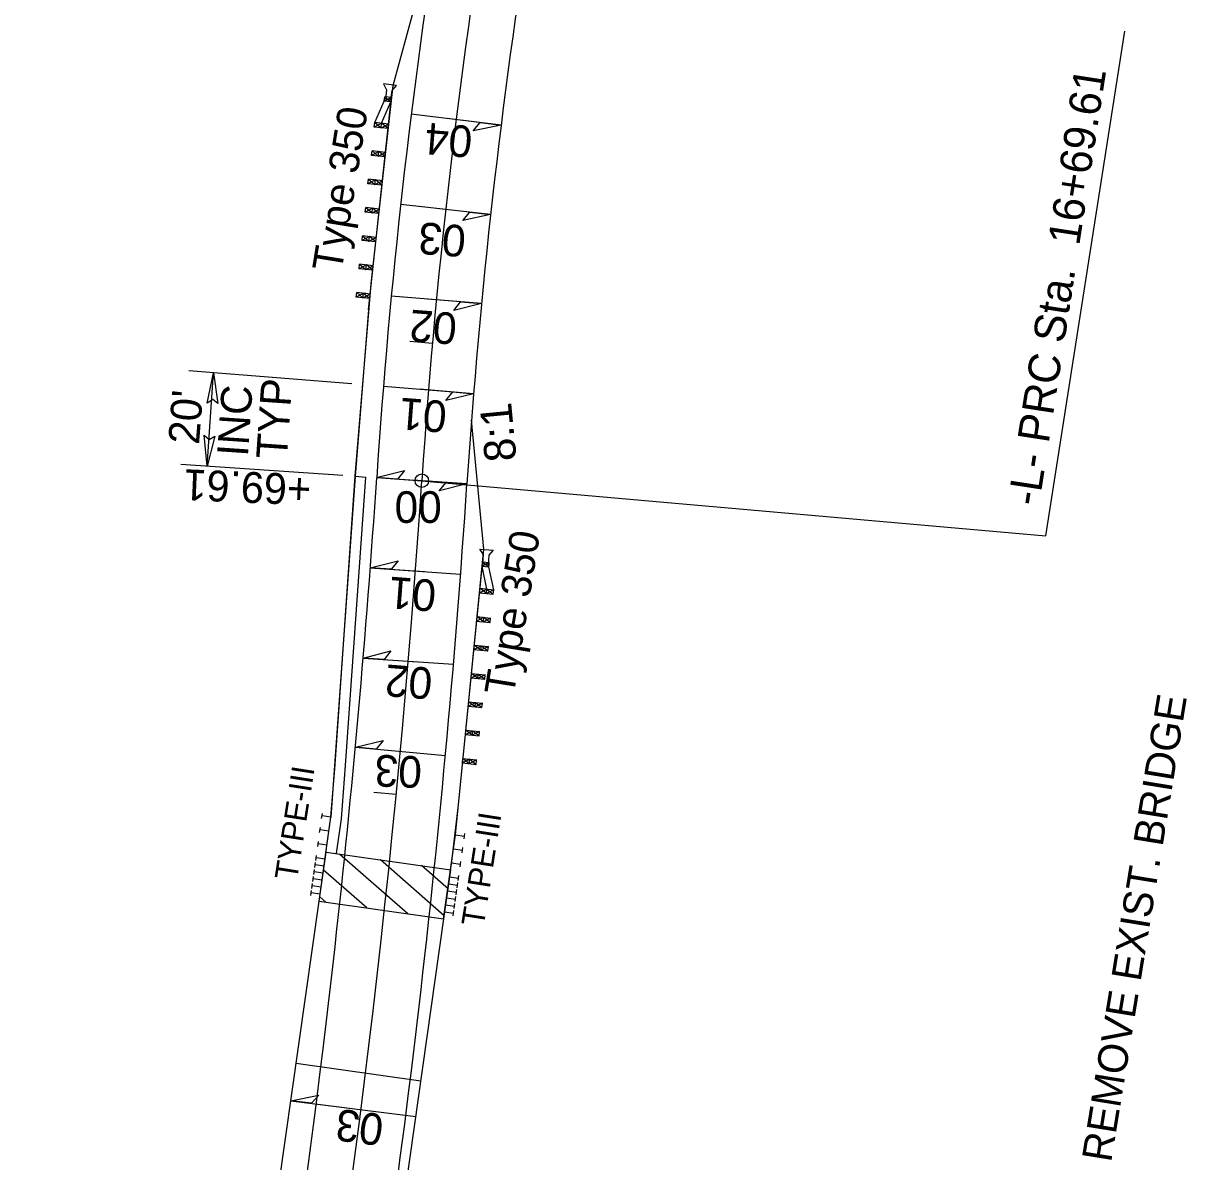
# Model space of a CAD drawing. Extents: x 1698814 to 1699654, y 708133 to 709468.
# Drawn here: x 1699331.8 to 1699588.9, y 708760.1 to 709011.7 of the extents above; entities that cross this region are included whole.
import ezdxf

# ---------------------------------------------------------------- set-up
doc = ezdxf.new("R2010")
doc.units = 0
for name, color, linetype in [('Prop Approach Slab', 7, 'Continuous'), ('Prop Approach Slab Hatching', 7, 'Continuous'), ('Prop Conc Shoulder Berm Gutter', 7, 'Continuous'), ('Prop Dimension', 7, 'Continuous'), ('Prop EOT', 7, 'Continuous'), ('Prop Guardrail', 7, 'Continuous'), ('Prop Guardrail Anchor Unit CELL', 7, 'Continuous'), ('Prop Horizontal Alignment', 7, 'Continuous'), ('Prop Horizontal Alignment Station Label', 7, 'Continuous'), ('Prop Horizontal Alignment Tick Small', 7, 'Continuous'), ('Prop Paved Shoulder', 7, 'Continuous'), ('Prop Roadway Bridge', 7, 'Continuous'), ('Prop Structure Anchor Unit CELL', 7, 'Continuous'), ('Prop Superelevation  Arrow CELL', 7, 'Continuous'), ('Prop Superelevation Label', 7, 'Continuous'), ('Prop Terminator CELL', 7, 'Continuous')]:
    doc.layers.add(name, color=color, linetype=linetype)

msp = doc.modelspace()

# ---------------------------------------------------------------- linework, layer by layer
at = {"layer": 'Prop Approach Slab'}
for p, q in [((1699397.2, 708817.65), (1699398.74, 708828.5)), ((1699398.74, 708828.5), (1699426.29, 708824.6)), ((1699424.76, 708813.74), (1699426.3, 708824.6))]:
    msp.add_line(p, q, dxfattribs=at)
at = {"layer": 'Prop Approach Slab Hatching'}
for p, q in [((1699416.8, 708814.87), (1699401.72, 708828.08)), ((1699407.74, 708816.15), (1699398.18, 708824.54)), ((1699424.86, 708814.45), (1699410.77, 708826.8)), ((1699425.79, 708820.29), (1699419.82, 708825.51)), ((1699398.69, 708817.44), (1699397.36, 708818.6))]:
    msp.add_line(p, q, dxfattribs=at)
at = {"layer": 'Prop Conc Shoulder Berm Gutter'}
for p, q in [((1699400.72, 708847.85), (1699405.21, 708911.57)), ((1699399.83, 708836.21), (1699400.72, 708847.85)), ((1699398.71, 708828.32), (1699399.83, 708836.21)), ((1699426.27, 708824.41), (1699426.55, 708826.39))]:
    msp.add_line(p, q, dxfattribs=at)
at = {"layer": 'Prop Dimension'}
for p, q in [((1699404.43, 708932.01), (1699368.45, 708934.91)), ((1699372.47, 708913.83), (1699373.88, 708934.48)), ((1699366.65, 708914.22), (1699402.43, 708911.79))]:
    msp.add_line(p, q, dxfattribs=at)
at = {"layer": 'Prop EOT'}
msp.add_line((1699411.63, 708815.6), (1699411.63, 708815.6), dxfattribs=at)
for centre, radius, start, end in [((1700816.84, 708818.02), 1410, 165.74431, 176.20849), ((1700816.84, 708818.02), 1390, 165.7259, 176.20849), ((1697132.82, 709061.2), 2282.04, 353.61848, 356.23256), ((1697124.94, 709062.69), 2310, 350.26654, 356.20849), ((1697132.82, 709061.2), 2282.04, 344.49766, 353.61848)]:
    msp.add_arc(centre, radius, start, end, dxfattribs=at)
at = {"layer": 'Prop Guardrail'}
for p, q in [((1699408.12, 708948.34), (1699405.21, 708911.57)), ((1699405.21, 708911.57), (1699399.83, 708836.21)), ((1699427.33, 708832.32), (1699428.65, 708845.67))]:
    msp.add_line(p, q, dxfattribs=at)
at = {"layer": 'Prop Guardrail Anchor Unit CELL'}
for p, q in [((1699414.32, 708997.95), (1699411.4, 708998.32)), ((1699411.4, 708998.32), (1699412.11, 708997.04)), ((1699412.11, 708997.04), (1699411.85, 708995.01)), ((1699413.06, 708994.86), (1699413.32, 708996.89)), ((1699413.32, 708996.89), (1699414.32, 708997.95)), ((1699408.12, 708948.34), (1699413.14, 708994.82)), ((1699409.51, 708989.78), (1699411.59, 708994.48)), ((1699411.03, 708989.61), (1699413.08, 708994.32)), ((1699411.59, 708994.48), (1699411.7, 708995.48)), ((1699413.19, 708995.32), (1699411.59, 708994.48)), ((1699411.59, 708994.48), (1699411.64, 708994.98)), ((1699413.08, 708994.32), (1699411.59, 708994.48)), ((1699413.19, 708995.32), (1699411.7, 708995.48)), ((1699411.7, 708995.48), (1699413.08, 708994.32)), ((1699411.85, 708995.01), (1699412.46, 708994.93)), ((1699412.46, 708994.93), (1699413.06, 708994.86)), ((1699409.4, 708988.78), (1699409.51, 708989.78)), ((1699411.03, 708989.61), (1699409.4, 708988.78)), ((1699412.56, 708989.45), (1699409.51, 708989.78)), ((1699409.51, 708989.78), (1699410.93, 708988.62)), ((1699410.93, 708988.62), (1699411.03, 708989.61)), ((1699410.93, 708988.62), (1699412.56, 708989.45)), ((1699412.45, 708988.45), (1699411.03, 708989.61)), ((1699412.45, 708988.45), (1699409.4, 708988.78)), ((1699408.79, 708982.51), (1699408.9, 708983.51)), ((1699410.39, 708983.34), (1699408.79, 708982.51)), ((1699411.77, 708982.19), (1699408.79, 708982.51)), ((1699411.88, 708983.18), (1699408.9, 708983.51)), ((1699408.9, 708983.51), (1699410.28, 708982.35)), ((1699410.28, 708982.35), (1699410.39, 708983.34)), ((1699410.28, 708982.35), (1699411.88, 708983.18)), ((1699411.77, 708982.19), (1699410.39, 708983.34)), ((1699407.98, 708976.26), (1699408.09, 708977.25)), ((1699409.65, 708977.09), (1699407.98, 708976.26)), ((1699411.1, 708975.92), (1699407.98, 708976.26)), ((1699411.21, 708976.92), (1699408.09, 708977.25)), ((1699408.09, 708977.25), (1699409.54, 708976.09)), ((1699409.54, 708976.09), (1699409.65, 708977.09)), ((1699409.54, 708976.09), (1699411.21, 708976.92)), ((1699411.1, 708975.92), (1699409.65, 708977.09)), ((1699407.4, 708969.98), (1699407.51, 708970.98)), ((1699410.53, 708970.65), (1699407.51, 708970.98)), ((1699407.51, 708970.98), (1699408.91, 708969.82)), ((1699409.02, 708970.82), (1699407.4, 708969.98)), ((1699410.42, 708969.66), (1699407.4, 708969.98)), ((1699408.91, 708969.82), (1699409.02, 708970.82)), ((1699408.91, 708969.82), (1699410.53, 708970.65)), ((1699410.42, 708969.66), (1699409.02, 708970.82)), ((1699410.42, 708969.66), (1699410.53, 708970.65)), ((1699406.72, 708963.72), (1699406.82, 708964.72)), ((1699408.34, 708964.55), (1699406.72, 708963.72)), ((1699409.75, 708963.39), (1699406.72, 708963.72)), ((1699409.85, 708964.39), (1699406.82, 708964.72)), ((1699406.82, 708964.72), (1699408.23, 708963.56)), ((1699408.23, 708963.56), (1699408.34, 708964.55)), ((1699408.23, 708963.56), (1699409.85, 708964.39)), ((1699409.75, 708963.39), (1699408.34, 708964.55)), ((1699406.04, 708957.46), (1699406.14, 708958.45)), ((1699407.66, 708958.29), (1699406.04, 708957.46)), ((1699409.18, 708958.12), (1699406.14, 708958.45)), ((1699406.14, 708958.45), (1699407.55, 708957.29)), ((1699407.55, 708957.29), (1699407.66, 708958.29)), ((1699407.55, 708957.29), (1699409.18, 708958.12)), ((1699409.07, 708957.13), (1699407.66, 708958.29)), ((1699409.07, 708957.13), (1699406.04, 708957.46)), ((1699405.41, 708951.19), (1699405.52, 708952.18)), ((1699407.01, 708952.02), (1699405.41, 708951.19)), ((1699408.4, 708950.86), (1699405.41, 708951.19)), ((1699408.5, 708951.86), (1699405.52, 708952.18)), ((1699405.52, 708952.18), (1699406.9, 708951.03)), ((1699406.9, 708951.03), (1699407.01, 708952.02)), ((1699406.9, 708951.03), (1699408.5, 708951.86)), ((1699408.5, 708951.86), (1699407.01, 708952.02)), ((1699407.01, 708952.02), (1699408.4, 708950.86)), ((1699408.4, 708950.86), (1699408.5, 708951.86)), ((1699433.53, 708894.26), (1699432.76, 708895.5)), ((1699432.76, 708895.5), (1699435.69, 708895.26)), ((1699433.36, 708892.21), (1699433.53, 708894.26)), ((1699434.74, 708894.15), (1699434.58, 708892.11)), ((1699435.69, 708895.26), (1699434.74, 708894.15)), ((1699428.65, 708845.67), (1699433.28, 708892.19)), ((1699434.82, 708892.54), (1699433.23, 708891.69)), ((1699433.23, 708891.69), (1699434.73, 708891.54)), ((1699434.27, 708886.66), (1699433.23, 708891.69)), ((1699433.33, 708892.69), (1699434.82, 708892.54)), ((1699433.33, 708892.69), (1699434.73, 708891.54)), ((1699433.97, 708892.16), (1699433.36, 708892.21)), ((1699434.58, 708892.11), (1699433.97, 708892.16)), ((1699434.73, 708891.54), (1699434.82, 708892.54)), ((1699434.73, 708891.54), (1699434.77, 708892.04)), ((1699435.8, 708886.51), (1699434.73, 708891.54)), ((1699432.65, 708885.82), (1699434.27, 708886.66)), ((1699432.75, 708886.82), (1699435.8, 708886.51)), ((1699434.17, 708885.67), (1699432.75, 708886.82)), ((1699434.17, 708885.67), (1699434.27, 708886.66)), ((1699435.8, 708886.51), (1699434.17, 708885.67)), ((1699434.27, 708886.66), (1699435.7, 708885.52)), ((1699435.7, 708885.52), (1699435.8, 708886.51)), ((1699432.65, 708885.82), (1699435.7, 708885.52)), ((1699432.02, 708879.55), (1699433.62, 708880.4)), ((1699432.02, 708879.55), (1699435.01, 708879.25)), ((1699432.12, 708880.55), (1699435.11, 708880.25)), ((1699433.52, 708879.4), (1699432.12, 708880.55)), ((1699433.52, 708879.4), (1699433.62, 708880.4)), ((1699435.11, 708880.25), (1699433.52, 708879.4)), ((1699433.62, 708880.4), (1699435.01, 708879.25)), ((1699435.01, 708879.25), (1699435.11, 708880.25)), ((1699431.4, 708873.28), (1699433.06, 708874.12)), ((1699431.4, 708873.28), (1699434.52, 708872.97)), ((1699431.5, 708874.27), (1699434.62, 708873.96)), ((1699432.96, 708873.12), (1699431.5, 708874.27)), ((1699432.96, 708873.12), (1699433.06, 708874.12)), ((1699434.62, 708873.96), (1699432.96, 708873.12)), ((1699433.06, 708874.12), (1699434.52, 708872.97)), ((1699434.52, 708872.97), (1699434.62, 708873.96)), ((1699430.78, 708867.01), (1699430.88, 708868)), ((1699430.78, 708867.01), (1699432.39, 708867.85)), ((1699430.78, 708867.01), (1699433.8, 708866.71)), ((1699430.88, 708868), (1699433.9, 708867.7)), ((1699432.29, 708866.86), (1699430.88, 708868)), ((1699432.29, 708866.86), (1699432.39, 708867.85)), ((1699433.9, 708867.7), (1699432.29, 708866.86)), ((1699432.39, 708867.85), (1699433.8, 708866.71)), ((1699433.8, 708866.71), (1699433.9, 708867.7)), ((1699430.15, 708860.74), (1699431.77, 708861.58)), ((1699430.15, 708860.74), (1699433.18, 708860.44)), ((1699430.25, 708861.73), (1699433.28, 708861.43)), ((1699431.67, 708860.59), (1699430.25, 708861.73)), ((1699431.67, 708860.59), (1699431.77, 708861.58)), ((1699433.28, 708861.43), (1699431.67, 708860.59)), ((1699431.77, 708861.58), (1699433.18, 708860.44)), ((1699433.18, 708860.44), (1699433.28, 708861.43)), ((1699429.53, 708854.47), (1699431.15, 708855.31)), ((1699429.63, 708855.46), (1699432.66, 708855.16)), ((1699431.05, 708854.32), (1699429.63, 708855.46)), ((1699431.05, 708854.32), (1699431.15, 708855.31)), ((1699431.15, 708855.31), (1699432.57, 708854.17)), ((1699429.53, 708854.47), (1699432.57, 708854.17)), ((1699432.66, 708855.16), (1699431.05, 708854.32)), ((1699432.57, 708854.17), (1699432.66, 708855.16)), ((1699428.9, 708848.2), (1699429, 708849.19)), ((1699430.5, 708849.05), (1699428.9, 708848.2)), ((1699428.9, 708848.2), (1699431.89, 708847.9)), ((1699429, 708849.19), (1699431.99, 708848.9)), ((1699429, 708849.19), (1699430.5, 708849.05)), ((1699430.4, 708848.05), (1699429, 708849.19)), ((1699430.4, 708848.05), (1699430.5, 708849.05)), ((1699431.99, 708848.9), (1699430.4, 708848.05)), ((1699430.5, 708849.05), (1699431.89, 708847.9)), ((1699431.89, 708847.9), (1699431.99, 708848.9))]:
    msp.add_line(p, q, dxfattribs=at)
at = {"layer": 'Prop Horizontal Alignment'}
for centre, radius, start, end in [((1700816.84, 708818.02), 1400, 164.19229, 176.20849), ((1697124.94, 709062.69), 2300, 343.70663, 356.20849)]:
    msp.add_arc(centre, radius, start, end, dxfattribs=at)
at = {"layer": 'Prop Horizontal Alignment Station Label'}
for p, q in [((1699557.79, 708898.43), (1699575.24, 709010)), ((1699419.9, 708910.6), (1699557.79, 708898.43))]:
    msp.add_line(p, q, dxfattribs=at)
msp.add_circle((1699419.9, 708910.6), 1.5, dxfattribs=at)
at = {"layer": 'Prop Horizontal Alignment Tick Small'}
for p, q in [((1699422.24, 708940.9), (1699417.26, 708941.34)), ((1699414.25, 708841.22), (1699409.27, 708841.7))]:
    msp.add_line(p, q, dxfattribs=at)
at = {"layer": 'Prop Paved Shoulder'}
for p, q in [((1699413.6, 708997.95), (1699423.64, 709035.08)), ((1699408.68, 708954.15), (1699413.6, 708997.95)), ((1699405.21, 708911.57), (1699408.68, 708954.15)), ((1699433.61, 708895.46), (1699430.88, 708924)), ((1699403.04, 708847.68), (1699407.53, 708911.41)), ((1699405.21, 708911.57), (1699407.53, 708911.41)), ((1699427.98, 708838.97), (1699433.61, 708895.46)), ((1699402.14, 708835.89), (1699403.04, 708847.66)), ((1699426.55, 708826.39), (1699427.98, 708838.97)), ((1699401.05, 708828.18), (1699402.14, 708835.89))]:
    msp.add_line(p, q, dxfattribs=at)
at = {"layer": 'Prop Roadway Bridge'}
for p, q in [((1699377.2, 708676.53), (1699397.2, 708817.65)), ((1699397.2, 708817.65), (1699424.7, 708813.75)), ((1699404.76, 708672.62), (1699424.76, 708813.74)), ((1699419.68, 708777.88), (1699392.12, 708781.78))]:
    msp.add_line(p, q, dxfattribs=at)
at = {"layer": 'Prop Structure Anchor Unit CELL'}
for p, q in [((1699397.2, 708817.65), (1699399.83, 708836.21)), ((1699397.77, 708835.93), (1699397.93, 708837.06)), ((1699399.83, 708836.21), (1699397.85, 708836.49)), ((1699397.33, 708832.83), (1699397.49, 708833.97)), ((1699399.39, 708833.12), (1699397.41, 708833.4)), ((1699424.7, 708813.75), (1699427.33, 708832.32)), ((1699427.33, 708832.32), (1699429.31, 708832.04)), ((1699429.23, 708831.47), (1699429.39, 708832.6)), ((1699396.89, 708829.74), (1699397.05, 708830.87)), ((1699398.95, 708830.03), (1699396.97, 708830.31)), ((1699428.79, 708828.37), (1699428.95, 708829.51)), ((1699396.46, 708826.64), (1699396.62, 708827.78)), ((1699398.52, 708826.93), (1699396.54, 708827.21)), ((1699426.89, 708829.22), (1699428.87, 708828.94)), ((1699396.02, 708823.55), (1699396.18, 708824.68)), ((1699396.24, 708825.1), (1699396.4, 708826.23)), ((1699398.3, 708825.38), (1699396.32, 708825.66)), ((1699426.45, 708826.13), (1699428.43, 708825.85)), ((1699428.35, 708825.28), (1699428.51, 708826.41)), ((1699395.8, 708822), (1699395.96, 708823.14)), ((1699397.86, 708822.29), (1699395.88, 708822.57)), ((1699398.08, 708823.84), (1699396.1, 708824.12)), ((1699426.01, 708823.03), (1699427.99, 708822.75)), ((1699427.91, 708822.19), (1699428.07, 708823.32)), ((1699395.36, 708818.91), (1699395.52, 708820.04)), ((1699397.42, 708819.2), (1699395.44, 708819.48)), ((1699395.58, 708820.46), (1699395.74, 708821.59)), ((1699397.64, 708820.74), (1699395.66, 708821.02)), ((1699425.57, 708819.94), (1699427.55, 708819.66)), ((1699425.79, 708821.49), (1699427.77, 708821.21)), ((1699427.47, 708819.09), (1699427.63, 708820.23)), ((1699427.69, 708820.64), (1699427.85, 708821.77)), ((1699425.13, 708816.85), (1699427.11, 708816.57)), ((1699425.35, 708818.39), (1699427.33, 708818.11)), ((1699427.03, 708816), (1699427.2, 708817.13)), ((1699427.25, 708817.55), (1699427.41, 708818.68)), ((1699424.92, 708815.3), (1699426.9, 708815.02)), ((1699426.82, 708814.45), (1699426.98, 708815.59))]:
    msp.add_line(p, q, dxfattribs=at)
at = {"layer": 'Prop Superelevation  Arrow CELL'}
for p, q in [((1699437.42, 708989.18), (1699425.51, 708990.66)), ((1699435.11, 708969.47), (1699423.18, 708970.77)), ((1699433.09, 708949.76), (1699421.13, 708950.73)), ((1699431.34, 708929.84), (1699419.38, 708930.8)), ((1699409.92, 708911.28), (1699421.9, 708910.46)), ((1699429.88, 708909.92), (1699417.91, 708910.73)), ((1699408.52, 708891.33), (1699420.5, 708890.51)), ((1699406.95, 708871.39), (1699418.92, 708870.57)), ((1699405.22, 708851.72), (1699417.17, 708850.61)), ((1699390.95, 708773.55), (1699402.85, 708772.03))]:
    msp.add_line(p, q, dxfattribs=at)
for points in [[(1699437.42, 708989.18), (1699431.22, 708987.93), (1699432.83, 708989.75)], [(1699435.11, 708969.47), (1699428.93, 708968.13), (1699430.52, 708969.97)], [(1699433.09, 708949.76), (1699426.95, 708948.25), (1699428.48, 708950.13)], [(1699431.34, 708929.84), (1699425.2, 708928.33), (1699426.73, 708930.21)], [(1699409.92, 708911.28), (1699416.05, 708912.86), (1699414.54, 708910.96)], [(1699429.88, 708909.92), (1699423.76, 708908.33), (1699425.26, 708910.23)], [(1699408.52, 708891.33), (1699414.65, 708892.91), (1699413.14, 708891.01)], [(1699406.95, 708871.39), (1699413.07, 708872.97), (1699411.56, 708871.07)], [(1699405.22, 708851.72), (1699411.38, 708853.16), (1699409.83, 708851.29)], [(1699390.95, 708773.55), (1699397.16, 708774.78), (1699395.54, 708772.97)]]:
    msp.add_lwpolyline(points, close=True, dxfattribs=at)
at = {"layer": 'Prop Superelevation Label'}
for p, q in [((1699437.42, 708989.18), (1699417.57, 708991.64)), ((1699435.11, 708969.47), (1699415.23, 708971.65)), ((1699433.09, 708949.76), (1699413.16, 708951.37)), ((1699431.34, 708929.84), (1699411.41, 708931.45)), ((1699409.92, 708911.28), (1699429.88, 708909.92)), ((1699408.52, 708891.33), (1699428.47, 708889.97)), ((1699406.95, 708871.39), (1699426.89, 708870.03)), ((1699405.22, 708851.72), (1699425.11, 708849.88)), ((1699390.95, 708773.55), (1699418.56, 708770.03))]:
    msp.add_line(p, q, dxfattribs=at)
at = {"layer": 'Prop Terminator CELL'}
for points in [[(1699372.5, 708927.77), (1699373.88, 708934.48), (1699374.86, 708927.65), (1699373.69, 708928.55)], [(1699374.14, 708920.47), (1699372.47, 708913.83), (1699371.79, 708920.69), (1699372.92, 708919.73)]]:
    msp.add_lwpolyline(points, close=True, dxfattribs=at)

# ---------------------------------------------------------------- texts
at = {"layer": 'Prop Dimension'}
for s, height, rotation, p in [('Type 350', 6.562, 80.7477, (1699402.14, 708956.56)), ('TYP', 6.825, 86.1035, (1699390.09, 708915.23)), ("20'", 6.825, 85.5197, (1699370.66, 708918.46)), ('INC', 6.825, 86.1035, (1699381.46, 708915.82)), ('8:1', 7, 95.4468, (1699440.86, 708915.14)), ('+69.61', 6.825, 177.5958, (1699395.58, 708911.96)), ('Type 350', 6.562, 80.7477, (1699440.18, 708862.86)), ('REMOVE EXIST. BRIDGE', 6.5625, 80.7477, (1699572.21, 708759.76))]:
    msp.add_text(s, height=height, rotation=rotation, dxfattribs=at).set_placement(p)
at = {"layer": 'Prop Horizontal Alignment Station Label'}
msp.add_text('-L- PRC Sta.  16+69.61', height=7, rotation=81.2267, dxfattribs=at).set_placement((1699556.27, 708904.82))
at = {"layer": 'Prop Structure Anchor Unit CELL'}
for p in [(1699392.31, 708822.11), (1699433.57, 708811.89)]:
    msp.add_text('TYPE-III', height=5, rotation=81.0546, dxfattribs=at).set_placement(p)
at = {"layer": 'Prop Superelevation Label'}
for s, rotation, p in [('04', 175.6067, (1699431.29, 708988.96)), ('03', 175.6067, (1699429.85, 708966.97)), ('02', 175.6067, (1699427.86, 708947.63)), ('01', 175.6067, (1699425.63, 708928.16)), ('01', 175.6067, (1699423.28, 708888.61)), ('02', 175.6067, (1699422.45, 708869.2)), ('03', 177.7543, (1699420.05, 708849.64)), ('03', 172.7286, (1699411.74, 708770.46))]:
    msp.add_text(s, height=7, rotation=rotation, dxfattribs=at).set_placement(p)
msp.add_text('00', height=7, dxfattribs=at).set_placement((1699413.89, 708901.27))

doc.saveas('drawing.dxf')
